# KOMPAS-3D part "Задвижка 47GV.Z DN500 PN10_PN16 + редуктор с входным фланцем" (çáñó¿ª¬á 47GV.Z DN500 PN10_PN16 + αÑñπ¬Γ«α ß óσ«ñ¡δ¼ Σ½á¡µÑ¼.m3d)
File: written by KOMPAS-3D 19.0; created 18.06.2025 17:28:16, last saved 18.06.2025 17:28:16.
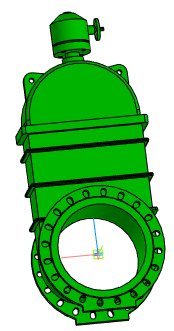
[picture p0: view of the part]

Document properties: Полное имя файла: Задвижка 47GV.Z DN500 PN10_PN16 + редуктор с входным валом.a3d

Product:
- Part/product: Задвижка 47GV.Z DN500 PN10_PN16 + редуктор с входным фланцем
    Масса: 1247.37
  - Body: Тело 1
      Масса: 1247.68

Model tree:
1. Операция без истории:1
